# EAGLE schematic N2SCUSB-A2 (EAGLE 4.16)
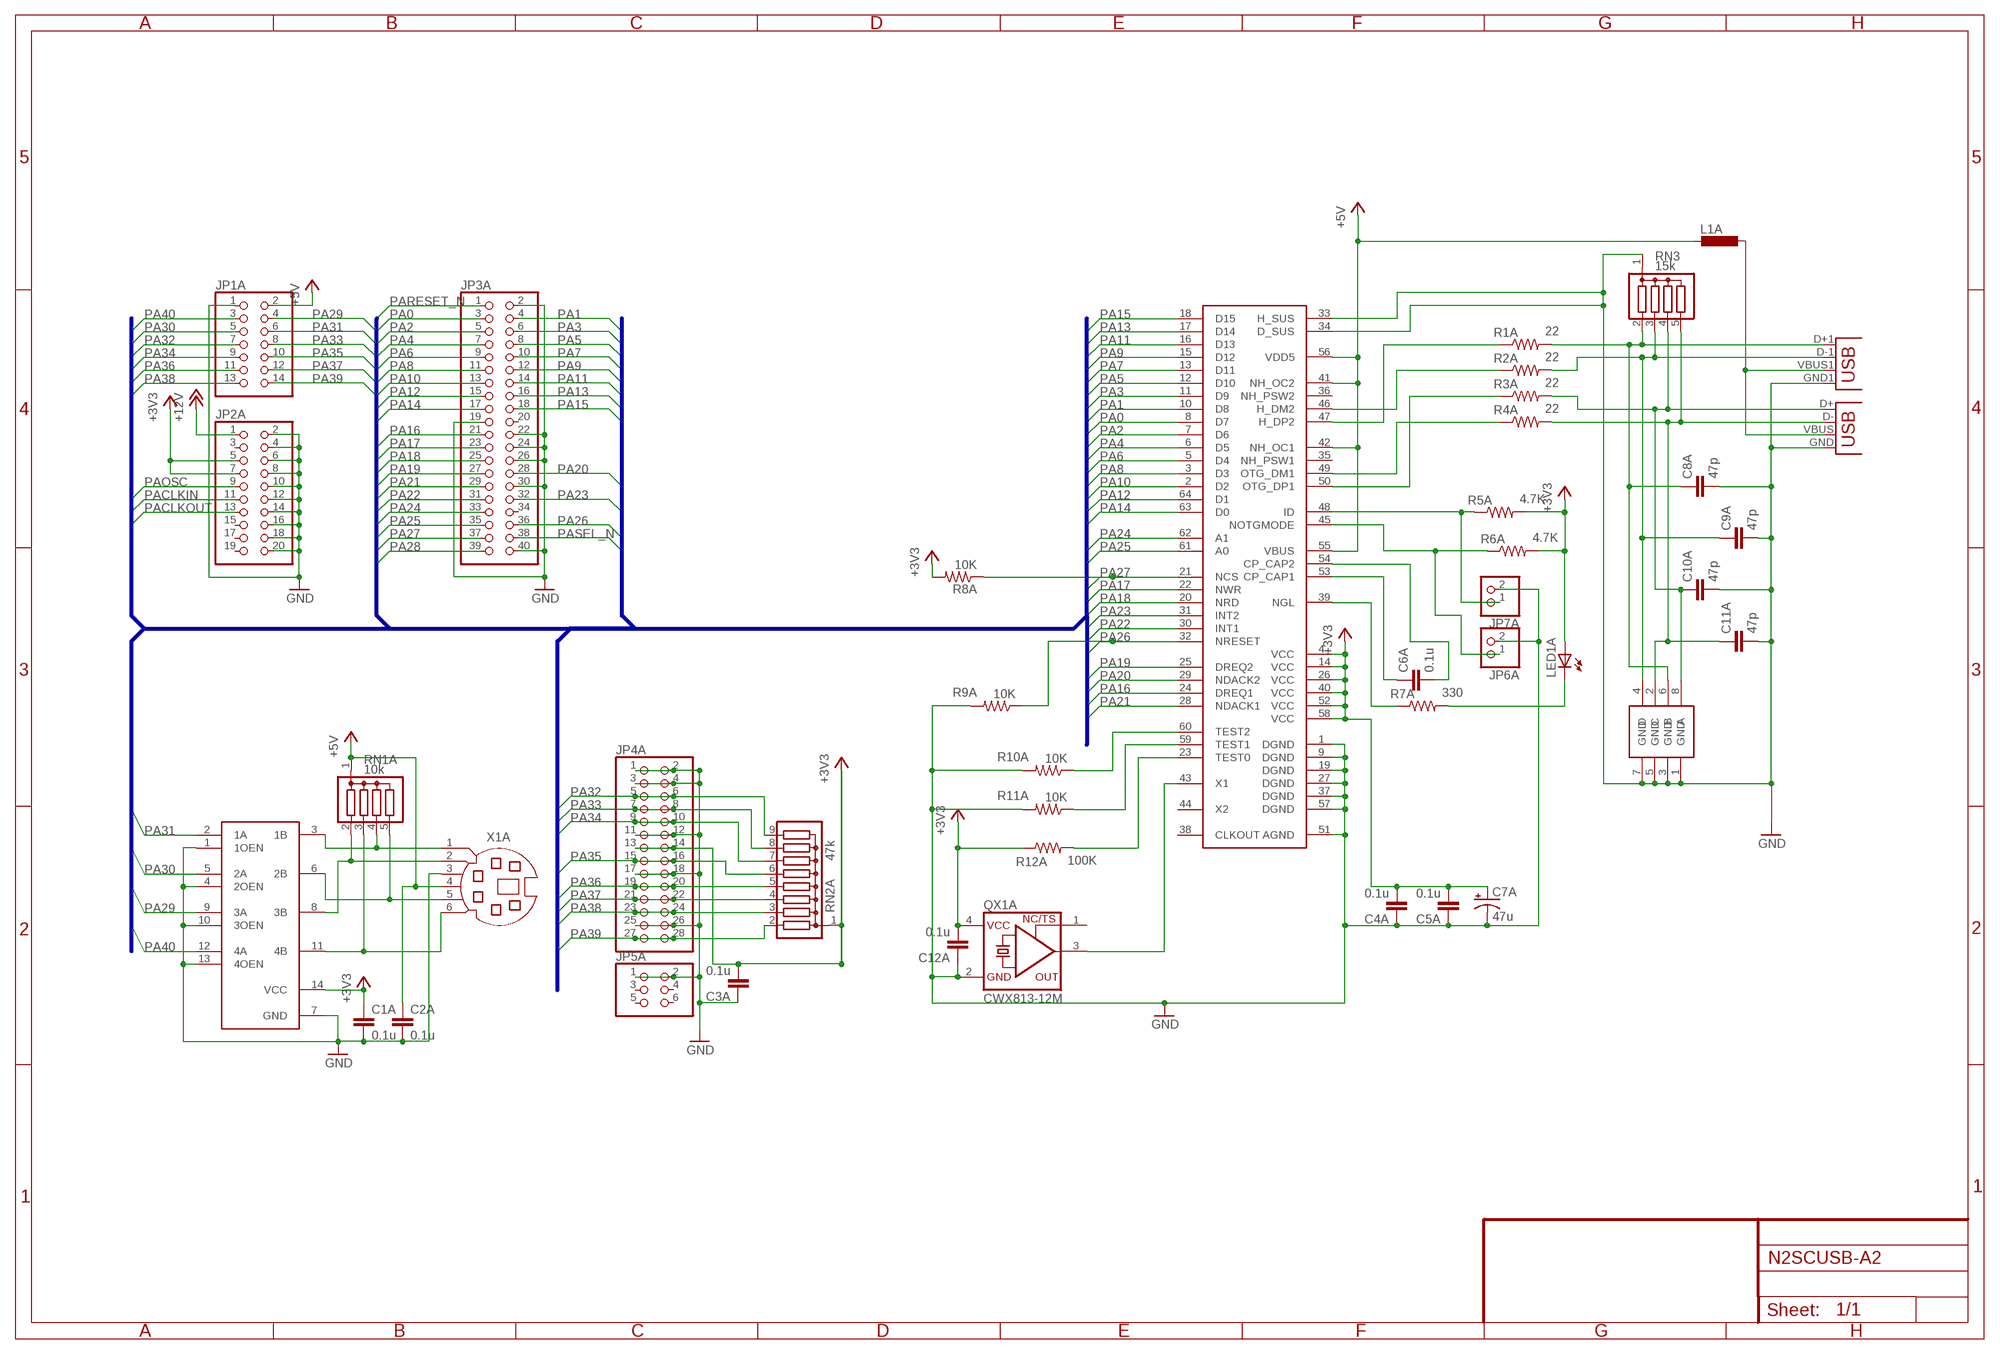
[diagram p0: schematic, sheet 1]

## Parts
C1A  0.1u  C-EU050-025X075  [C050-025X075]
C2A  0.1u  C-EU050-025X075  [C050-025X075]
C3A  0.1u  C-EU050-025X075  [C050-025X075]
C4A  0.1u  C-EU050-025X075  [C050-025X075]
C5A  0.1u  C-EU050-025X075  [C050-025X075]
C6A  0.1u  C-EU050-025X075  [C050-025X075]
C7A  47u  CPOL-USE3.5-10  [E3,5-10]
C8A  47p  C-EU025-025X050  [C025-025X050]
C9A  47p  C-EU025-025X050  [C025-025X050]
C10A  47p  C-EU025-025X050  [C025-025X050]
C11A  47p  C-EU025-025X050  [C025-025X050]
C12A  0.1u  C-EU050-025X075  [C050-025X075]
IC1A  CB3T3125  [TSSOP14]
IC2A  ISP1362S  [HTQFP-64A]
IC3A  75240  [TSSOP8]
JP1A  PINHD-2X7  [2X07]
JP2A  PINHD-2X10  [2X10]
JP3A  PINHD-2X20  [2X20]
JP4A  PINHD-2X14  [2X14]
JP5A  PINHD-2X3  [2X03]
JP6A  PINHD-1X2  [1X02]
JP7A  PINHD-1X2  [1X02]
L1A  L-EU0204/5  [0204/5]
LED1A  LED5MM  [LED5MM]
QX1A  CWX813-12M  CWX813  [CWX8W]
R1A  22  R-US_0204/5  [0204/5]
R2A  22  R-US_0204/5  [0204/5]
R3A  22  R-US_0204/5  [0204/5]
R4A  22  R-US_0204/5  [0204/5]
R5A  4.7K  R-US_0204/7  [0204/7]
R6A  4.7K  R-US_0204/7  [0204/7]
R7A  330  R-US_0204/7  [0204/7]
R8A  10K  R-US_0204/7  [0204/7]
R9A  10K  R-US_0204/7  [0204/7]
R10A  10K  R-US_0204/7  [0204/7]
R11A  10K  R-US_0204/7  [0204/7]
R12A  100K  R-US_0204/7  [0204/7]
RN1A  10k  G04R  [SIL5]
RN2A  47k  G08R  [SIL9]
RN3  15k  G04R  [SIL5]
X1A  MD06SS-  [MDIN06SSS]
X2A  USBX2  [USB-A-H-2]

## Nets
+3V3: C1A.1 C3A.2 C4A.2 C5A.2 C7A.+ C12A.2 IC1A.14(VCC) IC2A.4(VCC) IC2A.14(VCC) IC2A.26(VCC) IC2A.40(VCC) IC2A.52(VCC) IC2A.58(VCC) JP2A.5 JP2A.7 JP4A.13 JP4A.14 LED1A.A QX1A.4(VCC) R5A.2 R6A.2 R8A.2 R12A.1 RN2A.1
+5V: C2A.1 IC2A.41(NH_OC2) IC2A.42(NH_OC1) IC2A.55(VBUS) IC2A.56(VDD5) JP1A.2 L1A.2 RN1A.1 X1A.4
+12V: JP2A.1
GND: C1A.2 C2A.2 C3A.1 C4A.1 C5A.1 C7A.- C8A.2 C9A.2 C10A.2 C11A.2 C12A.1 IC1A.1(1OEN) IC1A.4(2OEN) IC1A.7(GND) IC1A.10(3OEN) IC1A.13(4OEN) IC2A.1(DGND) IC2A.9(DGND) IC2A.19(DGND) IC2A.27(DGND) IC2A.33(H_SUS) IC2A.34(D_SUS) IC2A.37(DGND) IC2A.51(AGND) IC2A.57(DGND) IC3A.1(GND) IC3A.3(GND) IC3A.5(GND) IC3A.7(GND) JP1A.1 JP2A.2 JP2A.4 JP2A.6 JP2A.8 JP2A.10 JP2A.12 JP2A.14 JP2A.16 JP2A.18 JP2A.20 JP3A.2 JP3A.19 JP3A.22 JP3A.24 JP3A.26 JP3A.30 JP3A.40 JP4A.1 JP4A.2 JP4A.3 JP4A.4 JP4A.11 JP4A.12 JP4A.17 JP4A.18 JP4A.25 JP4A.26 JP5A.1 JP5A.2 JP6A.2 JP7A.2 QX1A.2(GND) R9A.2 R10A.2 R11A.2 RN3.1 X1A.3 X2A.GND X2A.GND1
N$2: IC1A.3(1B) RN1A.4 X1A.1
N$4: C9A.1 IC3A.4(D) R2A.2 RN3.3 X2A.D-1
N$6: C8A.1 IC3A.6(B) R1A.2 RN3.2 X2A.D+1
N$7: IC2A.60(TEST2) R10A.1
N$12: L1A.1 X2A.VBUS X2A.VBUS1
N$13: IC1A.6(2B) RN1A.5 X1A.5
N$17: IC1A.8(3B) RN1A.2 X1A.2
N$18: IC1A.11(4B) RN1A.3 X1A.6
N$19: IC2A.43(X1) QX1A.3(OUT)
N$20: C10A.1 IC3A.8(A) R3A.2 RN3.4 X2A.D+
N$22: C11A.1 IC3A.2(C) R4A.2 RN3.5 X2A.D-
N$23: IC2A.46(H_DM2) R2A.1
N$25: IC2A.47(H_DP2) R1A.1
N$26: IC2A.49(OTG_DM1) R4A.1
N$29: IC2A.50(OTG_DP1) R3A.1
N$31: IC2A.39(NGL) R7A.1
N$34: IC2A.59(TEST1) R11A.1
N$35: IC2A.23(TEST0) R12A.2
N$36: LED1A.K(C) R7A.2
N$39: IC2A.48(ID) JP7A.1 R5A.1
N$40: IC2A.45(NOTGMODE) JP6A.1 R6A.1
N$42: C6A.2 IC2A.54(CP_CAP2)
N$43: C6A.1 IC2A.53(CP_CAP1)
PA0: IC2A.8(D7) JP3A.3
PA1: IC2A.10(D8) JP3A.4
PA2: IC2A.7(D6) JP3A.5
PA3: IC2A.11(D9) JP3A.6
PA4: IC2A.6(D5) JP3A.7
PA5: IC2A.12(D10) JP3A.8
PA6: IC2A.5(D4) JP3A.9
PA7: IC2A.13(D11) JP3A.10
PA8: IC2A.3(D3) JP3A.11
PA9: IC2A.15(D12) JP3A.12
PA10: IC2A.2(D2) JP3A.13
PA11: IC2A.16(D13) JP3A.14
PA12: IC2A.64(D1) JP3A.15
PA13: IC2A.17(D14) JP3A.16
PA14: IC2A.63(D0) JP3A.17
PA15: IC2A.18(D15) JP3A.18
PA16: IC2A.24(DREQ1) JP3A.21
PA17: IC2A.22(NWR) JP3A.23
PA18: IC2A.20(NRD) JP3A.25
PA19: IC2A.25(DREQ2) JP3A.27
PA20: IC2A.29(NDACK2) JP3A.28
PA21: IC2A.28(NDACK1) JP3A.29
PA22: IC2A.30(INT1) JP3A.31
PA23: IC2A.31(INT2) JP3A.32
PA24: IC2A.62(A1) JP3A.33
PA25: IC2A.61(A0) JP3A.35
PA26: IC2A.32(NRESET) JP3A.36 R9A.1
PA27: IC2A.21(NCS) JP3A.37 R8A.1
PA28: JP3A.39
PA29: IC1A.9(3A) JP1A.4
PA30: IC1A.5(2A) JP1A.5
PA31: IC1A.2(1A) JP1A.6
PA32: JP1A.7 JP4A.5 JP4A.6 RN2A.9
PA33: JP1A.8 JP4A.7 JP4A.8 RN2A.8
PA34: JP1A.9 JP4A.9 JP4A.10 RN2A.7
PA35: JP1A.10 JP4A.15 JP4A.16 RN2A.6
PA36: JP1A.11 JP4A.19 JP4A.20 RN2A.5
PA37: JP1A.12 JP4A.21 JP4A.22 RN2A.4
PA38: JP1A.13 JP4A.23 JP4A.24 RN2A.3
PA39: JP1A.14 JP4A.27 JP4A.28 RN2A.2
PA40: IC1A.12(4A) JP1A.3
PACLKIN: JP2A.11
PACLKOUT: JP2A.13
PAOSC: JP2A.9
PARESET_N: JP3A.1
PASEL_N: JP3A.38
Unconnected: IC2A.35(NH_PSW1) IC2A.36(NH_PSW2) IC2A.38(CLKOUT) IC2A.44(X2) JP2A.3 JP2A.15 JP2A.17 JP2A.19 JP3A.20 JP3A.34 JP5A.3 JP5A.4 JP5A.5 JP5A.6 QX1A.1(TS)

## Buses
PA[0..40],PASEL_N,PARESET_N,PAOSC,PACLKIN,PACLKOUT

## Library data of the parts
C1A C2A C3A C4A C5A C6A C8A C9A C10A C11A C12A = rcl:C-EU: CAPACITOR, European symbol
C7A = rcl:CPOL-US: POLARIZED CAPACITOR, American symbol
IC1A = texas_tfpxxx:CB3T3125
IC2A = philips_isp:ISP1362
IC3A = texas_tfpxxx:75240
JP1A = pinhead:PINHD-2X7: PIN HEADER
JP2A = pinhead:PINHD-2X10: PIN HEADER
JP3A = pinhead:PINHD-2X20: PIN HEADER
JP4A = pinhead:PINHD-2X14: PIN HEADER
JP5A = pinhead:PINHD-2X3: PIN HEADER
JP6A JP7A = pinhead:PINHD-1X2: PIN HEADER
L1A = rcl:L-EU: INDUCTOR, European symbol
LED1A = led:LED: LED
QX1A = crystal_smd:CWX813
R1A R2A R3A R4A R5A R6A R7A R8A R9A R10A R11A R12A = rcl:R-US_: RESISTOR, American symbol
RN1A RN3 = resistor-sil:G04R: SIL RESISTOR
RN2A = resistor-sil:G08R: SIL RESISTOR
X1A = con-yamaichi_DS6S:MD06SS: YAMAICHI CONNECTOR
X2A = con-usb:USBX2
